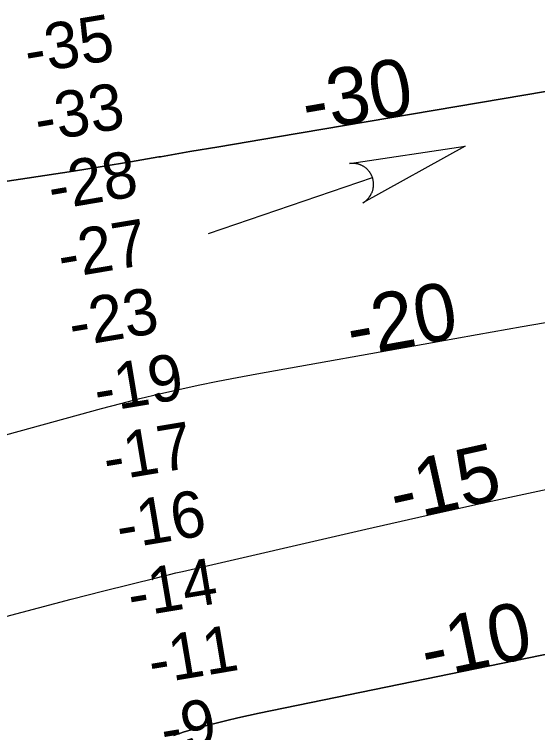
# Model space of a CAD drawing. Extents: x 3355677 to 3393573, y 612928 to 638357.
# Drawn here: x 3360499 to 3361256, y 622036 to 623074 of the extents above; entities that cross this region are included whole.
import ezdxf

# ---------------------------------------------------------------- set-up
doc = ezdxf.new("R2010")
doc.units = 0
for name, color, linetype in [('V-RIVR-RANG', 7, 'Continuous'), ('V-STRM-FLOW', 7, 'Continuous'), ('V-TOPO-DPTH', 7, 'Continuous'), ('V-TOPO-MINR', 7, 'Continuous'), ('V-TOPO-MINR-IDEN', 7, 'Continuous')]:
    doc.layers.add(name, color=color, linetype=linetype)

msp = doc.modelspace()

# ---------------------------------------------------------------- linework, layer by layer
at = {"layer": 'V-STRM-FLOW'}
msp.add_line((3360779.8, 622757.7), (3361016.9, 622838.3), dxfattribs=at)
msp.add_lwpolyline([(3360983.5, 622858.7), (3361150.9, 622884), (3361002.8, 622801.9), (3361005.4, 622803.5), (3361007.8, 622805.3), (3361008.6, 622806.1), (3361009.4, 622806.8), (3361010.3, 622807.7), (3361011.1, 622808.6), (3361011.8, 622809.4), (3361012.6, 622810.6), (3361013.5, 622811.9), (3361014, 622812.6), (3361014.6, 622813.6), (3361015.2, 622814.9), (3361015.7, 622815.9), (3361016.2, 622817), (3361016.5, 622817.8), (3361016.8, 622818.6), (3361017.2, 622819.7), (3361017.4, 622820.6), (3361017.7, 622821.6), (3361017.9, 622822.4), (3361018.1, 622823.6), (3361018.2, 622824.8), (3361018.3, 622825.7), (3361018.4, 622826.8), (3361018.5, 622827.8), (3361018.5, 622828.6), (3361018.5, 622829.3), (3361018.4, 622830.3), (3361018.4, 622831.3), (3361018.2, 622832.3), (3361018.1, 622833.3), (3361018, 622834.2), (3361017.8, 622835.1), (3361017.6, 622835.9), (3361017.3, 622837.1), (3361016.9, 622838.3), (3361016.7, 622838.7), (3361016.5, 622839.3), (3361016.2, 622840), (3361016, 622840.7), (3361015.7, 622841.3), (3361015.4, 622841.9), (3361015, 622842.6), (3361014.8, 622843.1), (3361014.4, 622843.8), (3361014, 622844.5), (3361013.7, 622844.9), (3361013, 622846), (3361012.5, 622846.6), (3361012.2, 622847), (3361011.7, 622847.6), (3361011.3, 622848.2), (3361010.8, 622848.8), (3361010.2, 622849.4), (3361009.6, 622850), (3361009.1, 622850.5), (3361008.7, 622850.9), (3361008.2, 622851.4), (3361007.6, 622851.8), (3361007, 622852.4), (3361006.4, 622852.8), (3361005.7, 622853.3), (3361004.9, 622853.9), (3361004.3, 622854.3), (3361003.6, 622854.7), (3361002.9, 622855.1), (3361002.3, 622855.5), (3361001.7, 622855.8), (3361000.7, 622856.2), (3361000.7, 622856.3), (3361000.1, 622856.5), (3360999.7, 622856.7), (3360999.1, 622856.9), (3360998.2, 622857.2), (3360997.6, 622857.5), (3360997, 622857.7), (3360996.3, 622857.9), (3360995.5, 622858.1), (3360995, 622858.2), (3360994.3, 622858.4), (3360993.4, 622858.5), (3360992.8, 622858.6), (3360992.3, 622858.7), (3360991.9, 622858.8), (3360991.4, 622858.8), (3360990.8, 622858.9), (3360990.1, 622858.9), (3360989.5, 622859), (3360988.8, 622859), (3360988, 622859), (3360987.5, 622859), (3360986.7, 622859), (3360985.8, 622858.9), (3360985.1, 622858.9), (3360984.6, 622858.8), (3360984.1, 622858.8), (3360983.8, 622858.7)], close=True, dxfattribs=at)
at = {"layer": 'V-TOPO-DPTH'}
for points in [[(3361689.2, 623025.5), (3361637.9, 623018.3), (3361586.5, 623011.3), (3361535.1, 623004.3), (3361466.6, 622995.1), (3361449.5, 622992.8), (3361432.4, 622990.3), (3361415.4, 622987.6), (3361398.3, 622984.8), (3360879.4, 622897.5), (3360837.1, 622890.3), (3360794.8, 622883.1), (3360752.6, 622875.9), (3360710.3, 622868.5), (3360708.1, 622868.2), (3360666.9, 622861.2), (3360625.7, 622854.3), (3360584.5, 622847.8), (3360543.2, 622841.4), (3360116.6, 622777.2)], [(3361689.2, 623025.5), (3361637.9, 623018.3), (3361586.5, 623011.3), (3361535.1, 623004.3), (3361466.6, 622995.1), (3361449.5, 622992.8), (3361432.4, 622990.3), (3361415.4, 622987.6), (3361398.3, 622984.8), (3360879.4, 622897.5), (3360837.1, 622890.3), (3360794.8, 622883.1), (3360752.6, 622875.9), (3360710.3, 622868.5), (3360708.1, 622868.2), (3360666.9, 622861.2), (3360625.7, 622854.3), (3360584.5, 622847.8), (3360543.2, 622841.4), (3360116.6, 622777.2)], [(3360057.1, 622348.6), (3360624.8, 622504.4), (3360652.7, 622511.8), (3360680.6, 622518.9), (3360708.6, 622525.7), (3360736.7, 622532.1), (3360764.9, 622538.2), (3360793.1, 622544), (3360821.4, 622549.5), (3360849.8, 622554.7), (3361103.8, 622600.2), (3361168.5, 622611.7), (3361233.2, 622623.1), (3361297.9, 622634.4)], [(3360057.1, 622348.6), (3360624.8, 622504.4), (3360652.7, 622511.8), (3360680.6, 622518.9), (3360708.6, 622525.7), (3360736.7, 622532.1), (3360764.9, 622538.2), (3360793.1, 622544), (3360821.4, 622549.5), (3360849.8, 622554.7), (3361103.8, 622600.2), (3361168.5, 622611.7), (3361233.2, 622623.1), (3361297.9, 622634.4)], [(3361943.5, 622290.8), (3361629.8, 622223.7), (3361601.9, 622217.7), (3361573.9, 622211.8), (3361546, 622206), (3361518, 622200.3), (3360853.2, 622064), (3360837.5, 622060.7), (3360821.9, 622057.3), (3360806.3, 622053.6), (3360790.8, 622049.9), (3360775.3, 622045.9), (3360759.9, 622041.6), (3360744.6, 622036.9), (3360729.4, 622032)], [(3361943.5, 622290.8), (3361629.8, 622223.7), (3361601.9, 622217.7), (3361573.9, 622211.8), (3361546, 622206), (3361518, 622200.3), (3360853.2, 622064), (3360837.5, 622060.7), (3360821.9, 622057.3), (3360806.3, 622053.6), (3360790.8, 622049.9), (3360775.3, 622045.9), (3360759.9, 622041.6), (3360744.6, 622036.9), (3360729.4, 622032)]]:
    msp.add_lwpolyline(points, dxfattribs=at)
at = {"layer": 'V-TOPO-MINR'}
for points in [[(3360116.6, 622777.2), (3360543.2, 622841.4), (3360584.5, 622847.8), (3360625.7, 622854.3), (3360666.9, 622861.2), (3360708.1, 622868.2), (3360710.3, 622868.5), (3360752.6, 622875.9), (3360794.8, 622883.1), (3360837.1, 622890.3), (3360879.4, 622897.5), (3361398.3, 622984.8), (3361415.4, 622987.6), (3361432.4, 622990.3), (3361449.5, 622992.8), (3361466.6, 622995.1), (3361535.1, 623004.3), (3361586.5, 623011.3), (3361637.9, 623018.3), (3361689.2, 623025.5)], [(3360057.1, 622348.6), (3360624.8, 622504.4), (3360652.7, 622511.8), (3360680.6, 622518.9), (3360708.6, 622525.7), (3360736.7, 622532.1), (3360764.9, 622538.2), (3360793.1, 622544), (3360821.4, 622549.5), (3360849.8, 622554.7), (3361103.8, 622600.2), (3361168.5, 622611.7), (3361233.2, 622623.1), (3361297.9, 622634.4)], [(3360486.4, 622203.7), (3360533.6, 622216.4), (3360580.9, 622228.7), (3360628.3, 622240.9), (3360704.3, 622260), (3360713.7, 622262.4), (3360723.1, 622264.7), (3360732.6, 622266.9), (3360742, 622269.1), (3361007.2, 622330), (3361094.5, 622349.7), (3361181.9, 622369.2), (3361269.5, 622388.1), (3361357.1, 622406.6), (3361456, 622427.2), (3361494.2, 622435.1), (3361532.5, 622442.9), (3361570.7, 622450.5), (3361609, 622458), (3362260.5, 622584.8)], [(3360729.4, 622032), (3360744.6, 622036.9), (3360759.9, 622041.6), (3360775.3, 622045.9), (3360790.8, 622049.9), (3360806.3, 622053.6), (3360821.9, 622057.3), (3360837.5, 622060.7), (3360853.2, 622064), (3361518, 622200.3), (3361546, 622206), (3361573.9, 622211.8), (3361601.9, 622217.7), (3361629.8, 622223.7), (3361943.5, 622290.8)]]:
    msp.add_lwpolyline(points, dxfattribs=at)

# ---------------------------------------------------------------- texts
at = {"layer": 'V-RIVR-RANG'}
for s, p in [('-35', (3360519, 622988.1)), ('-33', (3360533.7, 622889.2)), ('-28', (3360553.1, 622791)), ('-27', (3360567.3, 622692)), ('-23', (3360583.1, 622593.3)), ('-19', (3360619.4, 622498)), ('-17', (3360632.9, 622398.8)), ('-16', (3360651.8, 622300.6)), ('-14', (3360668.3, 622202)), ('-11', (3360698.2, 622105.6)), ('-9', (3360716, 622007.2))]:
    msp.add_text(s, height=67, rotation=9.5213, dxfattribs=at).set_placement(p)
at = {"layer": 'V-TOPO-MINR-IDEN'}
for s, rotation, p in [('-30', 9.5564, (3360921.5, 622904.6)), ('-20', 10.15, (3360986.7, 622579.3)), ('-15', 12.5225, (3361051.1, 622340.1)), ('-10', 11.5803, (3361095.3, 622113.6))]:
    msp.add_text(s, height=83, rotation=rotation, dxfattribs=at).set_placement(p)

doc.saveas('drawing.dxf')
